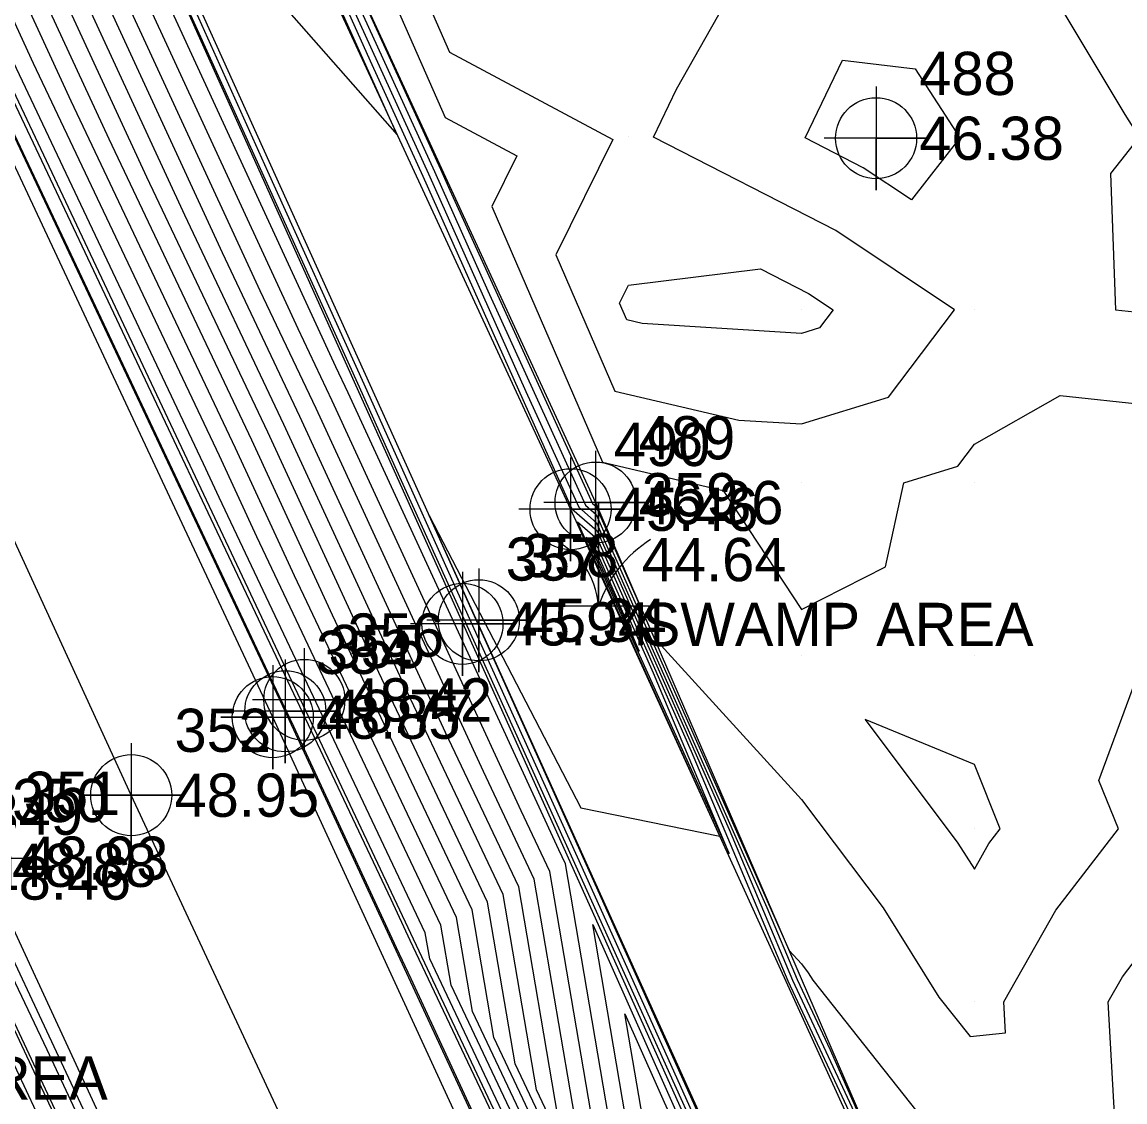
# Model space of a CAD drawing. Extents: x 2090860 to 2091277, y 159470 to 160080.
# Drawn here: x 2090944.9 to 2091008.7, y 159984.2 to 160046.6 of the extents above; entities that cross this region are included whole.
import ezdxf

# ---------------------------------------------------------------- set-up
doc = ezdxf.new("R2010")
doc.units = 0
for name, color, linetype in [('DTM Contours Major', 7, 'Continuous'), ('DTM Contours Minor', 7, 'Continuous'), ('Exist DTM Breakline', 7, 'Continuous'), ('Exist DTM Breakline Cogo Elevation', 7, 'Continuous'), ('Exist DTM Breakline Cogo Number', 7, 'Continuous'), ('Exist DTM Breakline Cogo Point CELL', 7, 'Continuous'), ('Exist DTM Crownline', 7, 'Continuous'), ('Exist DTM Crownline Cogo Elevation', 7, 'Continuous'), ('Exist DTM Crownline Cogo Number', 7, 'Continuous'), ('Exist DTM Crownline Cogo Point CELL', 7, 'Continuous'), ('Exist DTM QL2 LIDAR Elevation Point', 7, 'Continuous'), ('Exist DTM Regular Point CELL', 7, 'Continuous'), ('Exist DTM Regular Point Cogo Elevation', 7, 'Continuous'), ('Exist DTM Regular Point Cogo Number', 7, 'Continuous'), ('Exist Hydro Swamp or Marsh', 7, 'Continuous'), ('Exist Hydro Swamp or Marsh Cogo Comment', 7, 'Continuous'), ('Exist Hydro Swamp or Marsh Cogo Elevation', 7, 'Continuous'), ('Exist Hydro Swamp or Marsh Cogo Number', 7, 'Continuous'), ('Exist Roads EOP', 7, 'Continuous'), ('Exist Roads EOP Cogo Elevation', 7, 'Continuous'), ('Exist Roads EOP Cogo Number', 7, 'Continuous'), ('Exist Roads EOP Cogo Point CELL', 7, 'Continuous'), ('Exist Roads EOT', 7, 'Continuous'), ('Exist Roads EOT Cogo Elevation', 7, 'Continuous'), ('Exist Roads EOT Cogo Number', 7, 'Continuous'), ('Exist Roads EOT Cogo Point CELL', 7, 'Continuous')]:
    doc.layers.add(name, color=color, linetype=linetype)

msp = doc.modelspace()

# ---------------------------------------------------------------- linework, layer by layer
at = {"layer": 'DTM Contours Major'}
for points in [[(2090956.341, 160065.361), (2090956.351, 160065.306), (2090959.29, 160058.77), (2090968.77, 160038.007), (2090971.862, 160031.101), (2090977.516, 160018.706), (2090978.126, 160018.174), (2090989.29, 159992.953), (2090989.994, 159992.181), (2090990.384, 159991.663), (2090990.651, 159991.238), (2090998.867, 159980.879), (2091008.192, 159981.808), (2091007.743, 159990), (2091008.559, 159991.441), (2091010, 159993.309)], [(2091021.025, 159898.877), (2091011.639, 159919.455), (2091005.482, 159932.957), (2091005.012, 159933.952), (2090993.094, 159961.193), (2090992.991, 159961.428), (2090991.418, 159965.023), (2090992.968, 159961.452), (2090985.925, 159965.485), (2090984.33, 159968.87), (2090979.616, 159978.837), (2090976.348, 159997.974), (2090975.965, 159998.781), (2090963.783, 160025.207), (2090963.068, 160026.714), (2090951.202, 160052.433), (2090950.873, 160053.127), (2090947.083, 160061.339), (2090947.113, 160061.357)], [(2091021.18, 159890.907), (2091013.639, 159907.174), (2091008.516, 159918.108), (2091005.725, 159924.066), (2091001.855, 159932.408), (2090996.755, 159943.477), (2090989.564, 159959.773), (2090985.428, 159962.142), (2090982.708, 159967.911), (2090974.675, 159984.898), (2090972.744, 159996.202), (2090967.23, 160007.833), (2090960.061, 160023.383), (2090954.323, 160035.484), (2090947.368, 160050.56), (2090945.472, 160054.558), (2090943.253, 160059.365), (2090943.413, 160059.46)], [(2091015.949, 159893.794), (2091005.233, 159916.667), (2090999.394, 159929.129), (2090998.605, 159930.829), (2090988.204, 159953.404), (2090986.126, 159958.114), (2090984.93, 159958.799), (2090981.087, 159966.952), (2090969.734, 159990.958), (2090969.141, 159994.43), (2090958.495, 160016.884), (2090956.34, 160021.56), (2090945.578, 160044.255), (2090943.533, 160048.687), (2090940.07, 160055.988), (2090939.423, 160057.391), (2090939.712, 160057.563)], [(2090979.482, 160030.391), (2090980, 160031.433), (2090987.627, 160032.373), (2090990.412, 160030.947), (2090991.827, 160030), (2090991.041, 160028.959), (2090990, 160028.637), (2090980.782, 160029.218), (2090979.901, 160029.424), (2090979.482, 160030.391)], [(2090985.815, 159998.578), (2090981.439, 160009.001), (2090978.226, 160016.26), (2090977.546, 160016.853), (2090985.815, 159998.578)]]:
    msp.add_lwpolyline(points, dxfattribs=at)
at = {"layer": 'DTM Contours Minor'}
for points in [[(2090962.817, 160070.236), (2090966.182, 160061.546), (2090964.741, 160056.06), (2090969.648, 160044.9), (2090979.093, 160039.847), (2090975.783, 160033.187), (2090979.196, 160025.31), (2090986.367, 160023.633), (2090990, 160023.404), (2090995.039, 160024.961), (2090998.841, 160030), (2090991.992, 160034.585), (2090981.432, 160039.992), (2090982.77, 160042.77), (2090986.859, 160050), (2090990, 160053.765), (2090997.048, 160052.952), (2091000, 160051.642), (2091003.496, 160050), (2091008.694, 160041.306), (2091009.539, 160039.998), (2091007.882, 160037.882), (2091008.162, 160030), (2091010, 160029.803)], [(2090959.85, 160067.927), (2090961.603, 160063.399), (2090960.853, 160060.541), (2090969.388, 160041.128), (2090973.538, 160038.908), (2090972.083, 160035.982), (2090978.491, 160021.196), (2090985.462, 160019.565), (2090990, 160012.68), (2090994.856, 160015.144), (2090995.921, 160020), (2090999.037, 160020.963), (2091000, 160022.239), (2091004.956, 160025.044), (2091010, 160024.503), (2091013.768, 160026.232), (2091016.326, 160030), (2091016.342, 160033.658), (2091017.201, 160035.597), (2091017.93, 160038.105), (2091010.492, 160059.017)], [(2090956.883, 160065.619), (2090957.025, 160065.253), (2090956.964, 160065.022), (2090960.254, 160057.54), (2090969.111, 160038.143), (2090969.661, 160036.915), (2090977.917, 160018.813), (2090978.101, 160018.652), (2090981.469, 160011.044), (2090989.997, 160001.7), (2090994.717, 159995.42), (2090997.946, 159990.272), (2090999.751, 159987.996), (2091001.8, 159988.2), (2091001.701, 159990), (2091004.702, 159995.298), (2091008.33, 160000), (2091007.204, 160002.796), (2091009.862, 160010)], [(2090953.131, 160064.189), (2090950.324, 160062.823), (2090950.15, 160062.668), (2090953.104, 160055.485), (2090966.615, 160040.133), (2090955.458, 160064.946), (2090955.415, 160065.18)], [(2090955.723, 160065.24), (2090955.755, 160065.066), (2090965.14, 160044.195), (2090968.09, 160037.734), (2090976.266, 160019.474), (2090976.714, 160018.492), (2090978.176, 160017.217), (2090985.815, 159999.959), (2090989.474, 159991.243), (2090993.478, 159982.712), (2090997.759, 159973.016), (2091003.522, 159962), (2091011.65, 159946.449)], [(2090956.032, 160065.301), (2090956.053, 160065.186), (2090962.215, 160051.483), (2090968.43, 160037.87), (2090974.064, 160025.288), (2090977.115, 160018.599), (2090978.151, 160017.695), (2090988.003, 159995.439), (2090989.746, 159991.286), (2090991.654, 159987.221), (2090997.113, 159974.859), (2090997.983, 159973.762), (2090999.376, 159973.9), (2091008.084, 159970.483), (2091003.919, 159961.557), (2091011.802, 159946.475)], [(2091025.102, 159892.473), (2091012.728, 159918.738), (2091012.329, 159919.613), (2091012.067, 159920.187), (2091005.42, 159934.274), (2091005.163, 159934.86), (2090993.441, 159961.728), (2090992.08, 159964.838), (2090989.382, 159971.02), (2090984.007, 159982.894), (2090977.042, 159998.364), (2090971.588, 160010.408), (2090964.702, 160025.709), (2090959.133, 160037.996), (2090952.362, 160053.053), (2090950.665, 160056.795), (2090948.359, 160061.924), (2090950.641, 160063.035)], [(2091024.64, 159892.328), (2091016.876, 159908.808), (2091011.984, 159919.534), (2091008.774, 159926.572), (2091005.216, 159934.113), (2090999.129, 159948.027), (2090993.216, 159961.578), (2090990.478, 159967.834), (2090989.149, 159970.881), (2090979.664, 159991.834), (2090976.792, 159998.213), (2090966.504, 160020.929), (2090964.429, 160025.539), (2090952.994, 160050.772), (2090952.056, 160052.858), (2090948.153, 160061.461), (2090947.998, 160061.806), (2090948.151, 160061.88)], [(2091023.606, 159891.972), (2091011.906, 159917.209), (2091010.978, 159919.19), (2091010.473, 159920.269), (2091004.292, 159933.592), (2091003.168, 159936.032), (2090992.143, 159961.018), (2090985.801, 159964.649), (2090983.924, 159968.63), (2090978.381, 159980.353), (2090975.447, 159997.531), (2090973.781, 160001.044), (2090962.852, 160024.751), (2090960.882, 160028.906), (2090950.243, 160051.965), (2090949.523, 160053.484), (2090946.126, 160060.846), (2090946.188, 160060.883)], [(2091021.989, 159891.262), (2091013.061, 159910.519), (2091009.337, 159918.469), (2091007.307, 159922.8), (2091002.667, 159932.803), (2090998.893, 159940.995), (2090990.424, 159960.188), (2090985.552, 159962.978), (2090983.114, 159968.151), (2090975.91, 159983.383), (2090973.645, 159996.645), (2090969.414, 160005.57), (2090960.992, 160023.839), (2090956.509, 160033.292), (2090948.326, 160051.028), (2090946.822, 160054.2), (2090944.211, 160059.859), (2090944.338, 160059.934)], [(2091022.798, 159891.617), (2091012.484, 159913.864), (2091010.158, 159918.829), (2091008.89, 159921.535), (2091003.48, 159933.198), (2091001.03, 159938.513), (2090991.283, 159960.603), (2090985.677, 159963.813), (2090983.519, 159968.391), (2090977.145, 159981.868), (2090974.546, 159997.088), (2090971.598, 160003.307), (2090961.922, 160024.295), (2090958.696, 160031.099), (2090949.285, 160051.497), (2090948.173, 160053.842), (2090945.168, 160060.352), (2090945.263, 160060.408)], [(2091014.217, 159903.829), (2091007.695, 159917.748), (2091004.142, 159925.332), (2091001.042, 159932.013), (2090994.617, 159945.959), (2090988.704, 159959.359), (2090985.303, 159961.306), (2090982.303, 159967.671), (2090973.44, 159986.413), (2090971.844, 159995.759), (2090965.046, 160010.096), (2090959.131, 160022.927), (2090952.137, 160037.677), (2090946.409, 160050.092), (2090944.121, 160054.915), (2090942.296, 160058.872), (2090942.487, 160058.986)], [(2091015.372, 159897.139), (2091006.054, 159917.027), (2091000.976, 159927.863), (2090999.417, 159931.224), (2090990.342, 159950.923), (2090986.985, 159958.529), (2090985.054, 159959.635), (2090981.492, 159967.192), (2090970.969, 159989.443), (2090970.042, 159994.873), (2090960.679, 160014.622), (2090957.27, 160022.016), (2090947.764, 160042.063), (2090944.492, 160049.155), (2090941.421, 160055.631), (2090940.381, 160057.885), (2090940.637, 160058.037)], [(2091014.794, 159900.484), (2091006.874, 159917.387), (2091002.559, 159926.597), (2091000.23, 159931.619), (2090992.479, 159948.441), (2090987.845, 159958.944), (2090985.179, 159960.47), (2090981.898, 159967.432), (2090972.204, 159987.928), (2090970.943, 159995.316), (2090962.863, 160012.359), (2090958.2, 160022.472), (2090949.95, 160039.87), (2090945.45, 160049.623), (2090942.771, 160055.273), (2090941.338, 160058.378), (2090941.562, 160058.512)], [(2091016.527, 159890.449), (2091004.412, 159916.306), (2090997.811, 159930.395), (2090997.792, 159930.434), (2090986.066, 159955.886), (2090985.266, 159957.699), (2090984.806, 159957.963), (2090980.682, 159966.713), (2090968.499, 159992.473), (2090968.24, 159993.988), (2090956.311, 160019.147), (2090955.409, 160021.104), (2090943.391, 160046.448), (2090942.575, 160048.218), (2090938.72, 160056.346), (2090938.465, 160056.898), (2090938.787, 160057.089)], [(2091015.092, 159888.281), (2091005.494, 159908.792), (2091002.253, 159915.399), (2090998.196, 159923.671), (2090995.587, 159929.309), (2090993.655, 159934.254), (2090987.577, 159947.689), (2090983.614, 159956.284), (2090983.391, 159956.773), (2090979.397, 159965.44), (2090979.189, 159965.897), (2090967.415, 159991.324), (2090966.567, 159993.113), (2090960.639, 160005.911), (2090959.796, 160007.69), (2090947.752, 160033.198), (2090947.057, 160034.665), (2090937.109, 160055.735), (2090936.921, 160056.131), (2090936.936, 160056.14)], [(2091009.719, 159902.684), (2091003.488, 159915.918), (2091000.285, 159922.734), (2090996.873, 159929.981), (2090990.78, 159943.197), (2090984.364, 159957.258), (2090983.277, 159959.617), (2090980.176, 159966.423), (2090978.448, 159970.155), (2090967.363, 159993.547), (2090966.269, 159995.909), (2090955.847, 160017.91), (2090953.21, 160023.496), (2090943.221, 160044.585), (2090940.726, 160049.87), (2090937.604, 160056.462), (2090937.861, 160056.615)], [(2090918.443, 160047.072), (2090925.071, 160032.691), (2090928.75, 160024.871), (2090936.833, 160007.361), (2090941.384, 159997.661), (2090946.344, 159987.242), (2090948.128, 159983.436), (2090958.851, 159960.931), (2090960.998, 159956.352), (2090964.881, 159948.099), (2090965.492, 159946.787), (2090977.739, 159920.762), (2090978.261, 159919.644), (2090983.592, 159908.064), (2090984.057, 159907.047), (2090994.33, 159884.723)], [(2090916.214, 160045.934), (2090925.287, 160026.693), (2090926.714, 160023.863), (2090938.295, 159999.263), (2090939.55, 159996.755), (2090940.102, 159995.614), (2090946.263, 159982.47), (2090947.312, 159980.299), (2090959.023, 159955.318), (2090959.373, 159954.55), (2090963.43, 159945.83), (2090964.452, 159943.584), (2090976.07, 159918.621), (2090976.488, 159917.773), (2090981.889, 159906.077), (2090983.02, 159903.782)], [(2090917.335, 160046.443), (2090927.654, 160024.558), (2090927.75, 160024.369), (2090931.7, 160015.979), (2090940.501, 159997.22), (2090941.185, 159995.783), (2090947.222, 159982.907), (2090948.733, 159979.736), (2090959.976, 159955.756), (2090960.546, 159954.544), (2090964.408, 159946.258), (2090966.553, 159941.699), (2090977.104, 159919.081), (2090978.421, 159916.221), (2090982.884, 159906.464), (2090984.288, 159903.411)], [(2090992.375, 160044.45), (2090996.583, 160043.947), (2090999.167, 160039.948), (2090996.355, 160036.36), (2090993.572, 160038.223), (2090990.206, 160039.947), (2090992.375, 160044.45)], [(2091012.106, 159925.968), (2091007.685, 159935.502), (2091010.132, 159943.75), (2090994.374, 159961.259), (2090993.699, 159961.981), (2090993.523, 159962.203), (2090989.615, 159971.158), (2090988.349, 159973.954), (2090977.292, 159998.516), (2090976.671, 159999.886), (2090968.466, 160018.121), (2090977.233, 160001.212), (2090985.269, 159999.581), (2090977.053, 160017.74)], [(2090977.053, 160017.74), (2090978.201, 160016.738), (2090983.627, 160004.48), (2090989.202, 159991.2), (2090995.302, 159978.202), (2090997.608, 159972.979), (2091009.774, 159949.721)], [(2090980.613, 160010.277), (2090979.251, 160013.522), (2090978.251, 160015.781), (2090978.039, 160015.966), (2090980.613, 160010.277)], [(2091000.845, 159999.155), (2091001.498, 160000), (2091000, 160003.718), (2090993.687, 160006.313), (2090999.05, 159999.176), (2091000, 159997.662), (2091000.845, 159999.155)], [(2090977.922, 159994.472), (2090988.528, 159970.658), (2090991.852, 159962.998), (2090986.05, 159966.321), (2090984.735, 159969.11), (2090980.851, 159977.322), (2090977.922, 159994.472)], [(2090979.783, 159989.293), (2090988.123, 159970.567), (2090990.737, 159964.544), (2090986.174, 159967.156), (2090985.14, 159969.35), (2090982.086, 159975.807), (2090979.783, 159989.293)]]:
    msp.add_lwpolyline(points, dxfattribs=at)
at = {"layer": 'Exist DTM Breakline'}
for points in [[(2090956.622, 160065.416), (2090978.09, 160018.859), (2090997.895, 159973.05), (2091025.359, 159920.65)], [(2090955.177, 160064.832), (2090976.645, 160018.474), (2090997.432, 159972.935), (2091025.272, 159920.294)], [(2091060.143, 159819.743), (2091040.416, 159857.574), (2091023.862, 159892.084), (2091004.981, 159933.927), (2090988.922, 159970.746), (2090947.972, 160061.797)], [(2091061.634, 159820.633), (2091041.562, 159858.316), (2091025.181, 159892.498), (2091005.429, 159934.281), (2090989.687, 159971.201), (2090948.616, 160062.008)], [(2091054.851, 159814.302), (2091016.781, 159888.977), (2090997.773, 159930.425), (2090980.346, 159966.514), (2090937.845, 160056.578)], [(2091012.481, 159842.709), (2090995.611, 159879.293), (2090976.725, 159918.896), (2090959.8, 159955.653), (2090940.36, 159997.15), (2090917.627, 160046.575)]]:
    msp.add_lwpolyline(points, dxfattribs=at)
at = {"layer": 'Exist DTM Breakline Cogo Point CELL'}
for points in [[(2090978.09, 160021.859), (2090978.09, 160015.859), (2090978.09, 160018.859), (2090981.09, 160018.859), (2090975.09, 160018.859)], [(2090976.645, 160021.474), (2090976.645, 160015.474), (2090976.645, 160018.474), (2090979.645, 160018.474), (2090973.645, 160018.474)], [(2090970.389, 160014.848), (2090970.389, 160008.848), (2090970.389, 160011.848), (2090973.389, 160011.848), (2090967.389, 160011.848)], [(2090971.33, 160015.052), (2090971.33, 160009.052), (2090971.33, 160012.052), (2090974.33, 160012.052), (2090968.33, 160012.052)], [(2090961.243, 160010.449), (2090961.243, 160004.449), (2090961.243, 160007.449), (2090964.243, 160007.449), (2090958.243, 160007.449)]]:
    msp.add_lwpolyline(points, dxfattribs=at)
for centre in [(2090978.09, 160018.859), (2090976.645, 160018.474), (2090970.389, 160011.848), (2090971.33, 160012.052), (2090961.243, 160007.449)]:
    msp.add_circle(centre, 2.344, dxfattribs=at)
at = {"layer": 'Exist DTM Crownline'}
msp.add_lwpolyline([(2091041.896, 159807.58), (2091022.738, 159848.476), (2091006.16, 159884.052), (2090987.202, 159924.29), (2090970.349, 159960.929), (2090951.234, 160001.943), (2090928.333, 160051.748)], dxfattribs=at)
at = {"layer": 'Exist DTM Crownline Cogo Point CELL'}
msp.add_lwpolyline([(2090951.234, 160004.943), (2090951.234, 159998.943), (2090951.234, 160001.943), (2090954.234, 160001.943), (2090948.234, 160001.943)], dxfattribs=at)
msp.add_circle((2090951.234, 160001.943), 2.344, dxfattribs=at)
at = {"layer": 'Exist DTM QL2 LIDAR Elevation Point'}
for p, q in [((2090980, 160040), (2090980, 160040)), ((2090980, 160030), (2090980, 160030)), ((2090990, 160030), (2090990, 160030)), ((2091000, 160030), (2091000, 160030)), ((2090990, 160020), (2090990, 160020)), ((2091000, 160020), (2091000, 160020)), ((2090990, 160010), (2090990, 160010)), ((2091000, 160010), (2091000, 160010)), ((2091000, 160000), (2091000, 160000)), ((2091000, 159990), (2091000, 159990))]:
    msp.add_line(p, q, dxfattribs=at)
at = {"layer": 'Exist DTM Regular Point CELL'}
msp.add_lwpolyline([(2090994.312, 160042.925), (2090994.312, 160036.925), (2090994.312, 160039.925), (2090997.312, 160039.925), (2090991.312, 160039.925)], dxfattribs=at)
msp.add_circle((2090994.312, 160039.925), 2.344, dxfattribs=at)
at = {"layer": 'Exist Hydro Swamp or Marsh'}
msp.add_line((2090978.262, 160015.565), (2090978.262, 160015.565), dxfattribs=at)
msp.add_lwpolyline([(2090975.037, 160012.891), (2090978.263, 160012.891), (2090978.263, 160018.808), (2090978.263, 160012.891), (2090981.488, 160012.891)], dxfattribs=at)
for centre, radius, start, end in [((2090973.663, 160012.558), 4.612, 4.14034, 67.53497), ((2090985.104, 160010.618), 7.208, 122.12745, 161.62219)]:
    msp.add_arc(centre, radius, start, end, dxfattribs=at)
at = {"layer": 'Exist Roads EOP'}
for points in [[(2091050.887, 159811.953), (2091031.567, 159853.358), (2091015.44, 159888.433), (2090996.018, 159929.558), (2090979.118, 159965.859), (2090960.144, 160006.791), (2090936.877, 160056.11)], [(2091032.873, 159803.467), (2091013.956, 159843.468), (2090996.901, 159879.939), (2090978.321, 159919.673), (2090961.239, 159956.493), (2090941.84, 159997.888), (2090918.792, 160047.284)]]:
    msp.add_lwpolyline(points, dxfattribs=at)
at = {"layer": 'Exist Roads EOP Cogo Point CELL'}
msp.add_lwpolyline([(2090960.144, 160009.791), (2090960.144, 160003.791), (2090960.144, 160006.791), (2090963.144, 160006.791), (2090957.144, 160006.791)], dxfattribs=at)
msp.add_circle((2090960.144, 160006.791), 2.344, dxfattribs=at)
at = {"layer": 'Exist Roads EOT'}
for points in [[(2091050.358, 159811.619), (2091030.997, 159852.885), (2091014.318, 159887.944), (2090995.228, 159929.102), (2090978.274, 159965.509), (2090959.414, 160006.451), (2090936.296, 160055.791)], [(2091033.429, 159803.706), (2091014.624, 159843.758), (2090997.608, 159880.208), (2090978.895, 159919.952), (2090961.789, 159956.632), (2090942.516, 159998.302), (2090919.608, 160047.643)]]:
    msp.add_lwpolyline(points, dxfattribs=at)
at = {"layer": 'Exist Roads EOT Cogo Point CELL'}
for points in [[(2090959.414, 160009.451), (2090959.414, 160003.451), (2090959.414, 160006.451), (2090956.414, 160006.451), (2090962.414, 160006.451)], [(2090951.234, 160004.943), (2090951.234, 159998.943), (2090951.234, 160001.943), (2090948.234, 160001.943), (2090954.234, 160001.943)], [(2090942.516, 160001.302), (2090942.516, 159995.302), (2090942.516, 159998.302), (2090939.516, 159998.302), (2090945.516, 159998.302)]]:
    msp.add_lwpolyline(points, dxfattribs=at)
for centre in [(2090959.414, 160006.451), (2090951.234, 160001.943)]:
    msp.add_circle(centre, 2.344, dxfattribs=at)

# ---------------------------------------------------------------- texts
at = {"layer": 'Exist DTM Breakline Cogo Elevation'}
for s, p in [('45.46', (2090979.145, 160017.224)), ('46.36', (2090980.59, 160017.609)), ('45.34', (2090973.83, 160010.802)), ('45.94', (2090972.889, 160010.598)), ('48.42', (2090963.743, 160006.199)), ('48.46', (2090942.86, 159995.9))]:
    msp.add_text(s, height=2.5, dxfattribs=at).set_placement(p)
at = {"layer": 'Exist DTM Breakline Cogo Number'}
for s, p in [('489', (2090980.59, 160021.359)), ('490', (2090979.145, 160020.974)), ('357', (2090972.889, 160014.348)), ('358', (2090973.83, 160014.552)), ('356', (2090963.743, 160009.949)), ('349', (2090942.86, 159999.65))]:
    msp.add_text(s, height=2.5, dxfattribs=at).set_placement(p)
at = {"layer": 'Exist DTM Crownline Cogo Elevation'}
msp.add_text('48.95', height=2.5, dxfattribs=at).set_placement((2090953.734, 160000.693))
at = {"layer": 'Exist DTM Crownline Cogo Number'}
msp.add_text('353', height=2.5, dxfattribs=at).set_placement((2090953.734, 160004.443))
at = {"layer": 'Exist DTM Regular Point Cogo Elevation'}
msp.add_text('46.38', height=2.5, dxfattribs=at).set_placement((2090996.812, 160038.675))
at = {"layer": 'Exist DTM Regular Point Cogo Number'}
msp.add_text('488', height=2.5, dxfattribs=at).set_placement((2090996.812, 160042.425))
at = {"layer": 'Exist Hydro Swamp or Marsh Cogo Comment'}
for p in [(2090980.762, 160010.565), (2090927.211, 159984.333)]:
    msp.add_text('SWAMP AREA', height=2.5, dxfattribs=at).set_placement(p)
at = {"layer": 'Exist Hydro Swamp or Marsh Cogo Elevation'}
msp.add_text('44.64', height=2.5, dxfattribs=at).set_placement((2090980.762, 160014.315))
at = {"layer": 'Exist Hydro Swamp or Marsh Cogo Number'}
msp.add_text('359', height=2.5, dxfattribs=at).set_placement((2090980.762, 160018.065))
at = {"layer": 'Exist Roads EOP Cogo Elevation'}
for s, p in [('48.77', (2090962.644, 160005.541)), ('48.88', (2090944.34, 159996.638))]:
    msp.add_text(s, height=2.5, dxfattribs=at).set_placement(p)
at = {"layer": 'Exist Roads EOP Cogo Number'}
for s, p in [('355', (2090962.644, 160009.291)), ('350', (2090944.34, 160000.388))]:
    msp.add_text(s, height=2.5, dxfattribs=at).set_placement(p)
at = {"layer": 'Exist Roads EOT Cogo Elevation'}
for s, p in [('48.85', (2090961.914, 160005.201)), ('48.95', (2090953.734, 160000.693)), ('48.93', (2090945.016, 159997.052))]:
    msp.add_text(s, height=2.5, dxfattribs=at).set_placement(p)
at = {"layer": 'Exist Roads EOT Cogo Number'}
for s, p in [('354', (2090961.914, 160008.951)), ('352', (2090953.734, 160004.443)), ('351', (2090945.016, 160000.802))]:
    msp.add_text(s, height=2.5, dxfattribs=at).set_placement(p)

doc.saveas('drawing.dxf')
